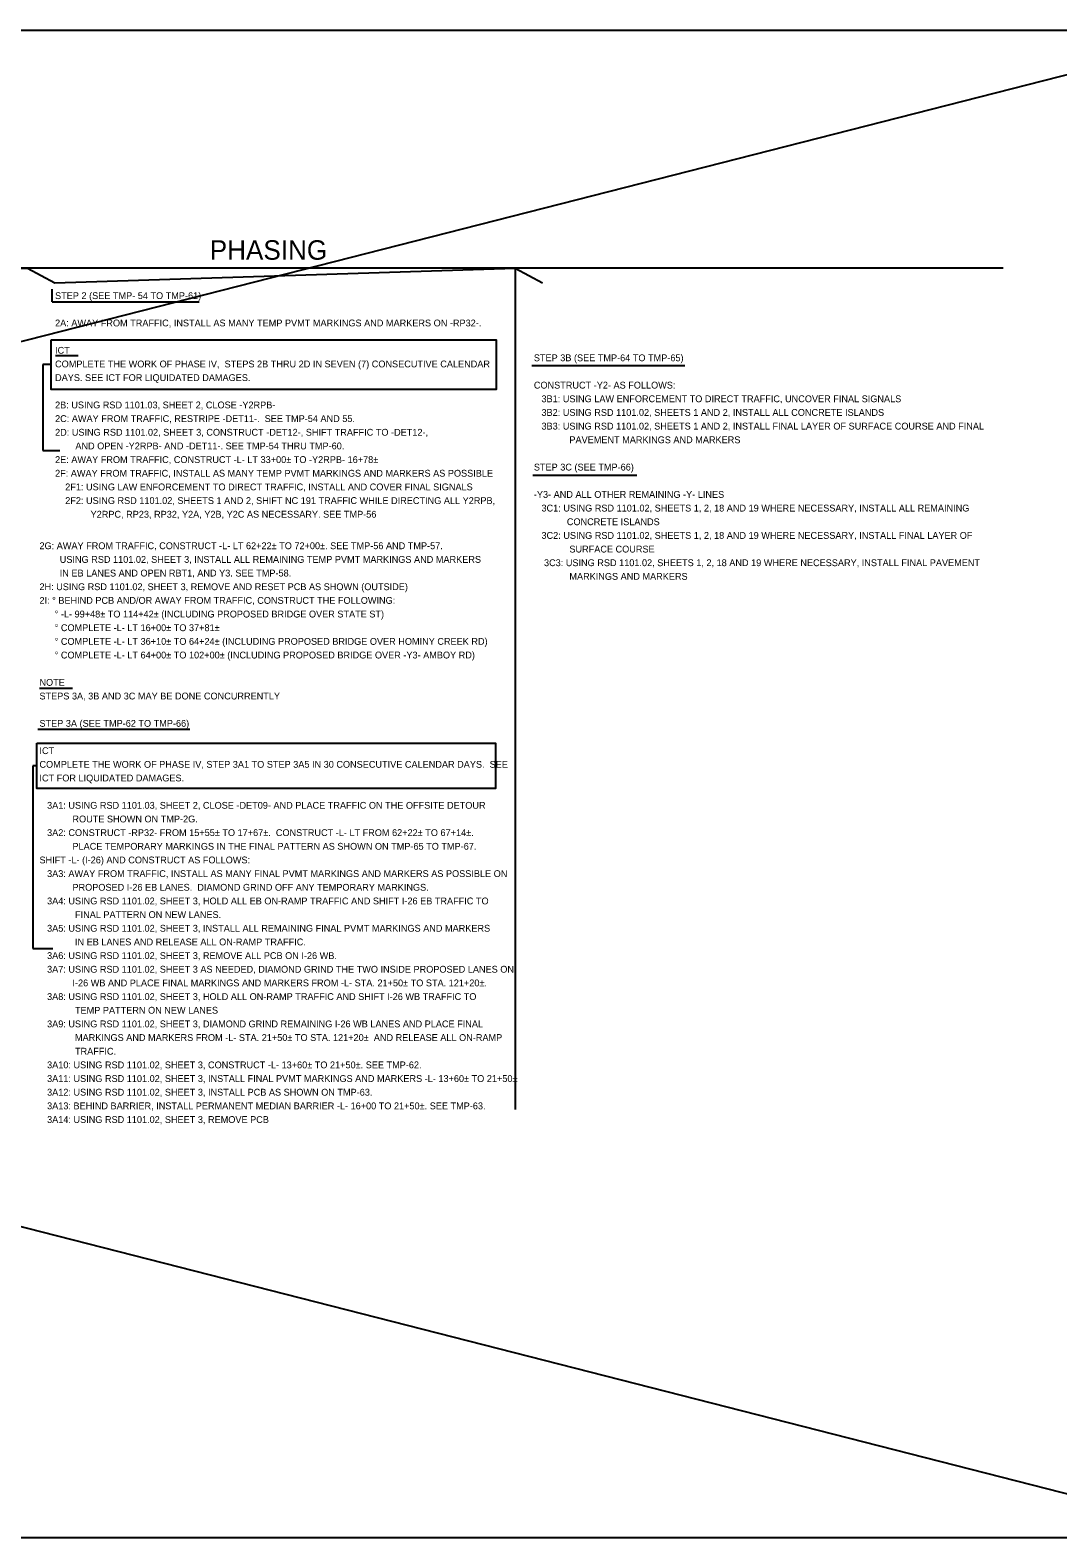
# Model space of a CAD drawing. Extents: x 2483905 to 2494512, y 366160 to 372330.
# Drawn here: x 2491514 to 2492568, y 368441 to 369986 of the extents above; entities that cross this region are included whole.
import ezdxf

# ---------------------------------------------------------------- set-up
doc = ezdxf.new("R2010")
doc.units = 0
for name, color, linetype in [('Prop Mkg Solid White Edge Line', 7, 'Continuous'), ('Scratch_Level_4', 7, 'Continuous'), ('Scratch_Level_6', 7, 'Continuous'), ('TC SHEET BORDER LINE THIN', 7, 'Continuous'), ('TC SHEET TEXT', 7, 'Continuous')]:
    doc.layers.add(name, color=color, linetype=linetype)

msp = doc.modelspace()

# ---------------------------------------------------------------- linework, layer by layer
at = {"layer": 'Prop Mkg Solid White Edge Line'}
for p, q in [((2491521.2, 369232.3), (2491517.2, 369232.3)), ((2491517.2, 369232.3), (2491517.2, 369232.3)), ((2491517.2, 369232.3), (2491517.2, 369045.1)), ((2491517.2, 369045.1), (2491517.2, 369045.1)), ((2491517.2, 369045.1), (2491537.6, 369045.1))]:
    msp.add_line(p, q, dxfattribs=at)
msp.add_lwpolyline([(2491521.2, 369255.4), (2491991.4, 369255.4), (2491991.4, 369209.2), (2491521.2, 369209.2)], close=True, dxfattribs=at)
at = {"layer": 'Scratch_Level_4'}
for p, q in [((2486701.2, 368441.1), (2492754.6, 369986.2)), ((2486701.2, 369986.2), (2492754.6, 368441.1))]:
    msp.add_line(p, q, dxfattribs=at)
msp.add_lwpolyline([(2486701.2, 369986.2), (2492754.6, 369986.2), (2492754.6, 368441.1), (2486701.2, 368441.1)], close=True, dxfattribs=at)
at = {"layer": 'Scratch_Level_6'}
msp.add_lwpolyline([(2491011.6, 369742.3), (2491039.5, 369727.3), (2491511.6, 369742.3), (2491539.5, 369727.3), (2492011.6, 369742.3), (2492039.5, 369727.3)], dxfattribs=at)
at = {"layer": 'TC SHEET BORDER LINE THIN'}
for p, q in [((2492511.6, 369742.3), (2491011.6, 369742.3)), ((2492011.6, 369742.3), (2492011.6, 368880.2)), ((2491536.9, 369707.8), (2491536.9, 369720.6)), ((2491536.9, 369707.8), (2491687.6, 369707.8)), ((2491536, 369643.5), (2491527.5, 369643.5)), ((2491527.5, 369643.5), (2491527.5, 369555.3)), ((2491540.2, 369652.9), (2491563.6, 369652.9)), ((2492028.5, 369642.5), (2492185.2, 369642.5)), ((2491527.5, 369584.6), (2491527.5, 369584.6)), ((2491527.5, 369555.3), (2491544.9, 369555.3)), ((2492029.4, 369530.2), (2492136.1, 369530.2)), ((2491523.8, 369312), (2491557.9, 369312)), ((2491522.2, 369269.7), (2491678, 369269.7))]:
    msp.add_line(p, q, dxfattribs=at)
msp.add_lwpolyline([(2491536, 369669), (2491991.9, 369669), (2491991.9, 369618), (2491536, 369618)], close=True, dxfattribs=at)

# ---------------------------------------------------------------- texts
for s, p in [('STEP 2 (SEE TMP- 54 TO TMP-61)', (2491539.9, 369710.6)), ('2A: AWAY FROM TRAFFIC, INSTALL AS MANY TEMP PVMT MARKINGS AND MARKERS ON -RP32-.', (2491539.9, 369682.6)), ('ICT', (2491539.9, 369654.6)), ('COMPLETE THE WORK OF PHASE IV,  STEPS 2B THRU 2D IN SEVEN (7) CONSECUTIVE CALENDAR', (2491539.9, 369640.6)), ('STEP 3B (SEE TMP-64 TO TMP-65)', (2492030.6, 369646.9)), ('DAYS. SEE ICT FOR LIQUIDATED DAMAGES.', (2491539.9, 369626.6)), ('CONSTRUCT -Y2- AS FOLLOWS:', (2492030.6, 369618.9)), ('   3B1: USING LAW ENFORCEMENT TO DIRECT TRAFFIC, UNCOVER FINAL SIGNALS', (2492030.6, 369604.9)), ('2B: USING RSD 1101.03, SHEET 2, CLOSE -Y2RPB- ', (2491539.9, 369598.6)), ('   3B2: USING RSD 1101.02, SHEETS 1 AND 2, INSTALL ALL CONCRETE ISLANDS', (2492030.6, 369590.9)), ('2C: AWAY FROM TRAFFIC, RESTRIPE -DET11-.  SEE TMP-54 AND 55.', (2491539.9, 369584.6)), ('   3B3: USING RSD 1101.02, SHEETS 1 AND 2, INSTALL FINAL LAYER OF SURFACE COURSE AND FINAL', (2492030.6, 369576.9)), ('2D: USING RSD 1101.02, SHEET 3, CONSTRUCT -DET12-, SHIFT TRAFFIC TO -DET12-, ', (2491539.9, 369570.6)), ('              PAVEMENT MARKINGS AND MARKERS', (2492030.6, 369562.9)), ('        AND OPEN -Y2RPB- AND -DET11-. SEE TMP-54 THRU TMP-60.', (2491539.9, 369556.6)), ('2E: AWAY FROM TRAFFIC, CONSTRUCT -L- LT 33+00± TO -Y2RPB- 16+78±', (2491539.9, 369542.6)), ('2F: AWAY FROM TRAFFIC, INSTALL AS MANY TEMP PVMT MARKINGS AND MARKERS AS POSSIBLE', (2491539.9, 369528.6)), ('STEP 3C (SEE TMP-66)', (2492030.6, 369534.9)), ('    2F1: USING LAW ENFORCEMENT TO DIRECT TRAFFIC, INSTALL AND COVER FINAL SIGNALS', (2491539.9, 369514.6)), ('    2F2: USING RSD 1101.02, SHEETS 1 AND 2, SHIFT NC 191 TRAFFIC WHILE DIRECTING ALL Y2RPB,', (2491539.9, 369500.6)), ('-Y3- AND ALL OTHER REMAINING -Y- LINES', (2492030.6, 369506.9)), ('              Y2RPC, RP23, RP32, Y2A, Y2B, Y2C AS NECESSARY. SEE TMP-56', (2491539.9, 369486.6)), ('   3C1: USING RSD 1101.02, SHEETS 1, 2, 18 AND 19 WHERE NECESSARY, INSTALL ALL REMAINING', (2492030.6, 369492.9)), ('             CONCRETE ISLANDS', (2492030.6, 369478.9)), ('2G: AWAY FROM TRAFFIC, CONSTRUCT -L- LT 62+22± TO 72+00±. SEE TMP-56 AND TMP-57.', (2491523.9, 369454.3)), ('   3C2: USING RSD 1101.02, SHEETS 1, 2, 18 AND 19 WHERE NECESSARY, INSTALL FINAL LAYER OF', (2492030.6, 369464.9)), ('              SURFACE COURSE', (2492030.6, 369450.9)), ('        USING RSD 1101.02, SHEET 3, INSTALL ALL REMAINING TEMP PVMT MARKINGS AND MARKERS', (2491523.9, 369440.3)), ('    3C3: USING RSD 1101.02, SHEETS 1, 2, 18 AND 19 WHERE NECESSARY, INSTALL FINAL PAVEMENT', (2492030.6, 369436.9)), ('        IN EB LANES AND OPEN RBT1, AND Y3. SEE TMP-58.', (2491523.9, 369426.3)), ('              MARKINGS AND MARKERS', (2492030.6, 369422.9)), ('2H: USING RSD 1101.02, SHEET 3, REMOVE AND RESET PCB AS SHOWN (OUTSIDE)', (2491523.9, 369412.3)), ('2I: ° BEHIND PCB AND/OR AWAY FROM TRAFFIC, CONSTRUCT THE FOLLOWING:', (2491523.9, 369398.3)), ('      ° -L- 99+48± TO 114+42± (INCLUDING PROPOSED BRIDGE OVER STATE ST)', (2491523.9, 369384.3)), ('      ° COMPLETE -L- LT 16+00± TO 37+81±', (2491523.9, 369370.3)), ('      ° COMPLETE -L- LT 36+10± TO 64+24± (INCLUDING PROPOSED BRIDGE OVER HOMINY CREEK RD)', (2491523.9, 369356.3)), ('      ° COMPLETE -L- LT 64+00± TO 102+00± (INCLUDING PROPOSED BRIDGE OVER -Y3- AMBOY RD)', (2491523.9, 369342.3)), ('NOTE', (2491523.9, 369314.3)), ('STEPS 3A, 3B AND 3C MAY BE DONE CONCURRENTLY', (2491523.9, 369300.3)), ('STEP 3A (SEE TMP-62 TO TMP-66)', (2491523.9, 369272.3)), ('ICT', (2491523.9, 369244.3)), ('COMPLETE THE WORK OF PHASE IV, STEP 3A1 TO STEP 3A5 IN 30 CONSECUTIVE CALENDAR DAYS.  SEE', (2491523.9, 369230.3)), ('ICT FOR LIQUIDATED DAMAGES.', (2491523.9, 369216.3)), ('   3A1: USING RSD 1101.03, SHEET 2, CLOSE -DET09- AND PLACE TRAFFIC ON THE OFFSITE DETOUR', (2491523.9, 369188.3)), ('             ROUTE SHOWN ON TMP-2G.', (2491523.9, 369174.3)), ('   3A2: CONSTRUCT -RP32- FROM 15+55± TO 17+67±.  CONSTRUCT -L- LT FROM 62+22± TO 67+14±.', (2491523.9, 369160.3)), ('             PLACE TEMPORARY MARKINGS IN THE FINAL PATTERN AS SHOWN ON TMP-65 TO TMP-67.', (2491523.9, 369146.3)), ('SHIFT -L- (I-26) AND CONSTRUCT AS FOLLOWS:', (2491523.9, 369132.3)), ('   3A3: AWAY FROM TRAFFIC, INSTALL AS MANY FINAL PVMT MARKINGS AND MARKERS AS POSSIBLE ON', (2491523.9, 369118.3)), ('             PROPOSED I-26 EB LANES.  DIAMOND GRIND OFF ANY TEMPORARY MARKINGS.', (2491523.9, 369104.3)), ('   3A4: USING RSD 1101.02, SHEET 3, HOLD ALL EB ON-RAMP TRAFFIC AND SHIFT I-26 EB TRAFFIC TO', (2491523.9, 369090.3)), ('              FINAL PATTERN ON NEW LANES.', (2491523.9, 369076.3)), ('   3A5: USING RSD 1101.02, SHEET 3, INSTALL ALL REMAINING FINAL PVMT MARKINGS AND MARKERS', (2491523.9, 369062.3)), ('   3A6: USING RSD 1101.02, SHEET 3, REMOVE ALL PCB ON I-26 WB.', (2491523.9, 369034.3)), ('              IN EB LANES AND RELEASE ALL ON-RAMP TRAFFIC.', (2491523.9, 369048.3)), ('   3A7: USING RSD 1101.02, SHEET 3 AS NEEDED, DIAMOND GRIND THE TWO INSIDE PROPOSED LANES ON ', (2491523.9, 369020.3)), ('             I-26 WB AND PLACE FINAL MARKINGS AND MARKERS FROM -L- STA. 21+50± TO STA. 121+20±.', (2491523.9, 369006.3)), ('   3A8: USING RSD 1101.02, SHEET 3, HOLD ALL ON-RAMP TRAFFIC AND SHIFT I-26 WB TRAFFIC TO', (2491523.9, 368992.3)), ('              TEMP PATTERN ON NEW LANES', (2491523.9, 368978.3)), ('   3A9: USING RSD 1101.02, SHEET 3, DIAMOND GRIND REMAINING I-26 WB LANES AND PLACE FINAL', (2491523.9, 368964.3)), ('              MARKINGS AND MARKERS FROM -L- STA. 21+50± TO STA. 121+20±  AND RELEASE ALL ON-RAMP ', (2491523.9, 368950.3)), ('              TRAFFIC.', (2491523.9, 368936.3)), ('   3A10: USING RSD 1101.02, SHEET 3, CONSTRUCT -L- 13+60± TO 21+50±. SEE TMP-62.', (2491523.9, 368922.3)), ('   3A11: USING RSD 1101.02, SHEET 3, INSTALL FINAL PVMT MARKINGS AND MARKERS -L- 13+60± TO 21+50±', (2491523.9, 368908.3)), ('   3A12: USING RSD 1101.02, SHEET 3, INSTALL PCB AS SHOWN ON TMP-63.', (2491523.9, 368894.3)), ('   3A13: BEHIND BARRIER, INSTALL PERMANENT MEDIAN BARRIER -L- 16+00 TO 21+50±. SEE TMP-63.', (2491523.9, 368880.3)), ('   3A14: USING RSD 1101.02, SHEET 3, REMOVE PCB', (2491523.9, 368866.3))]:
    msp.add_text(s, height=7, dxfattribs=at).set_placement(p)
at = {"layer": 'TC SHEET TEXT'}
msp.add_text('PHASING', height=20, rotation=359.9999, dxfattribs=at).set_placement((2491698.4, 369750.9))

doc.saveas('drawing.dxf')
